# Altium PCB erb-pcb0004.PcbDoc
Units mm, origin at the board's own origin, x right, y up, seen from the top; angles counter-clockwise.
Board outline 37 x 24 mm, 4 copper layers (Top Layer, Signal_1, Signal_2, Top Bottom), stack 1.57 mm thick; 26 components, 49 nets, 129 pads, 38 vias.
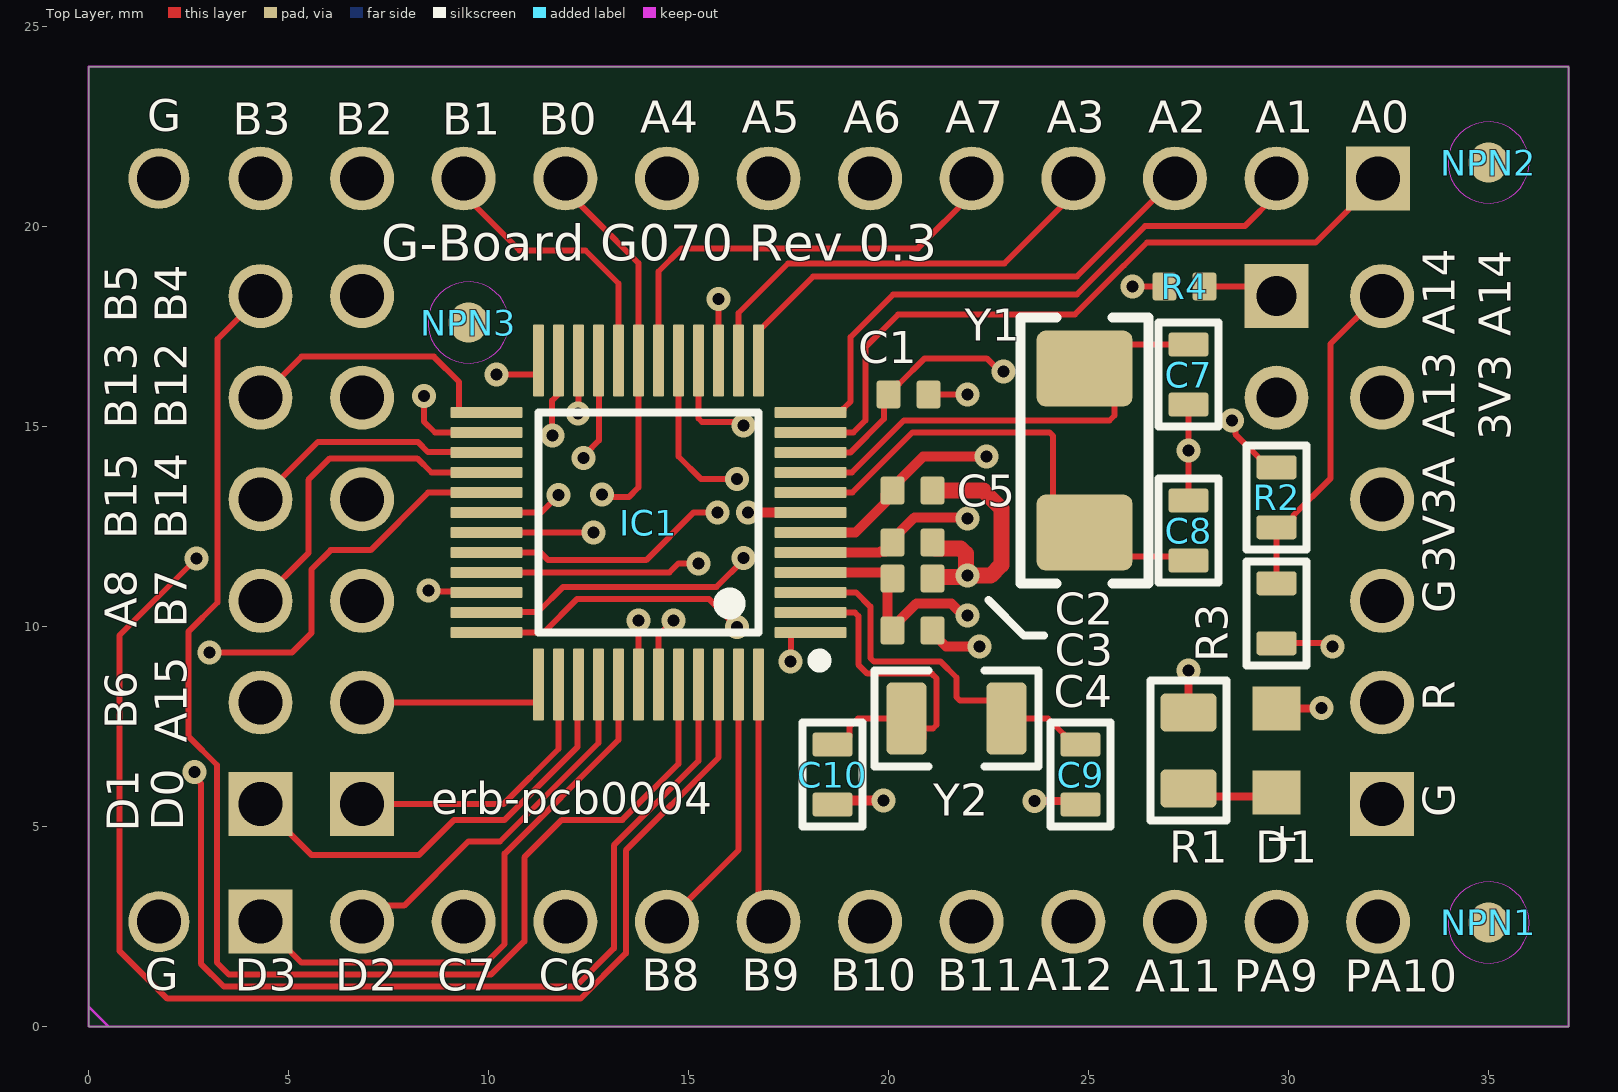
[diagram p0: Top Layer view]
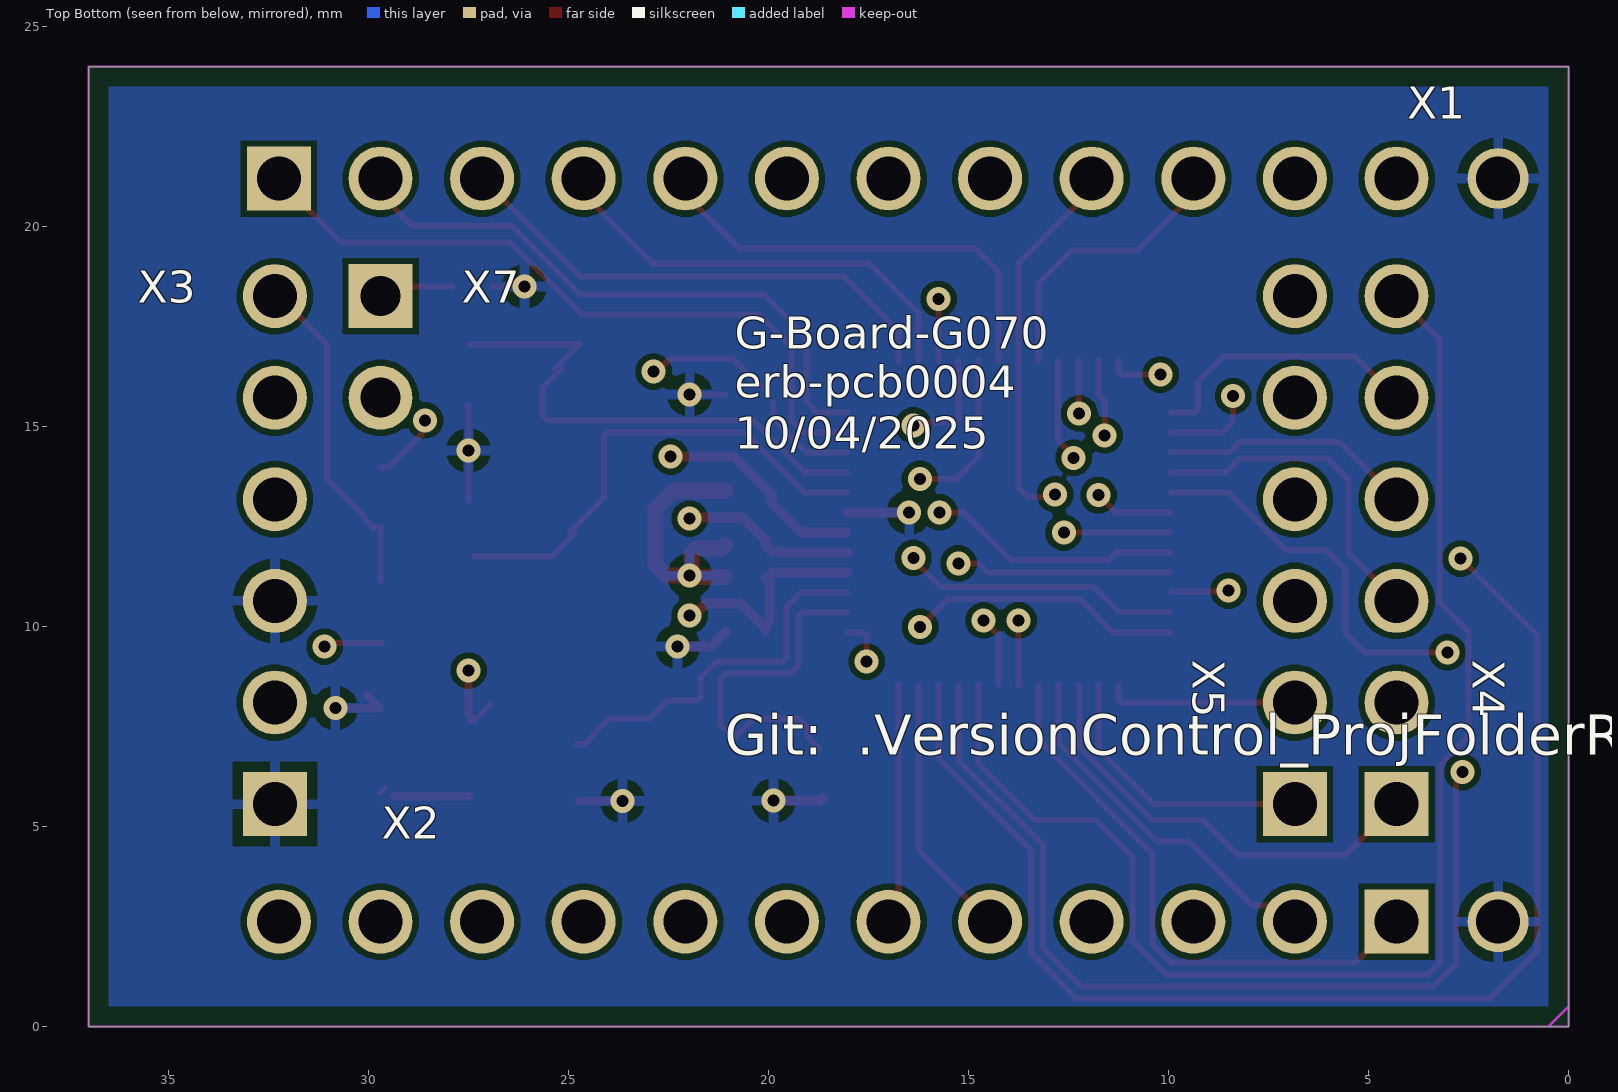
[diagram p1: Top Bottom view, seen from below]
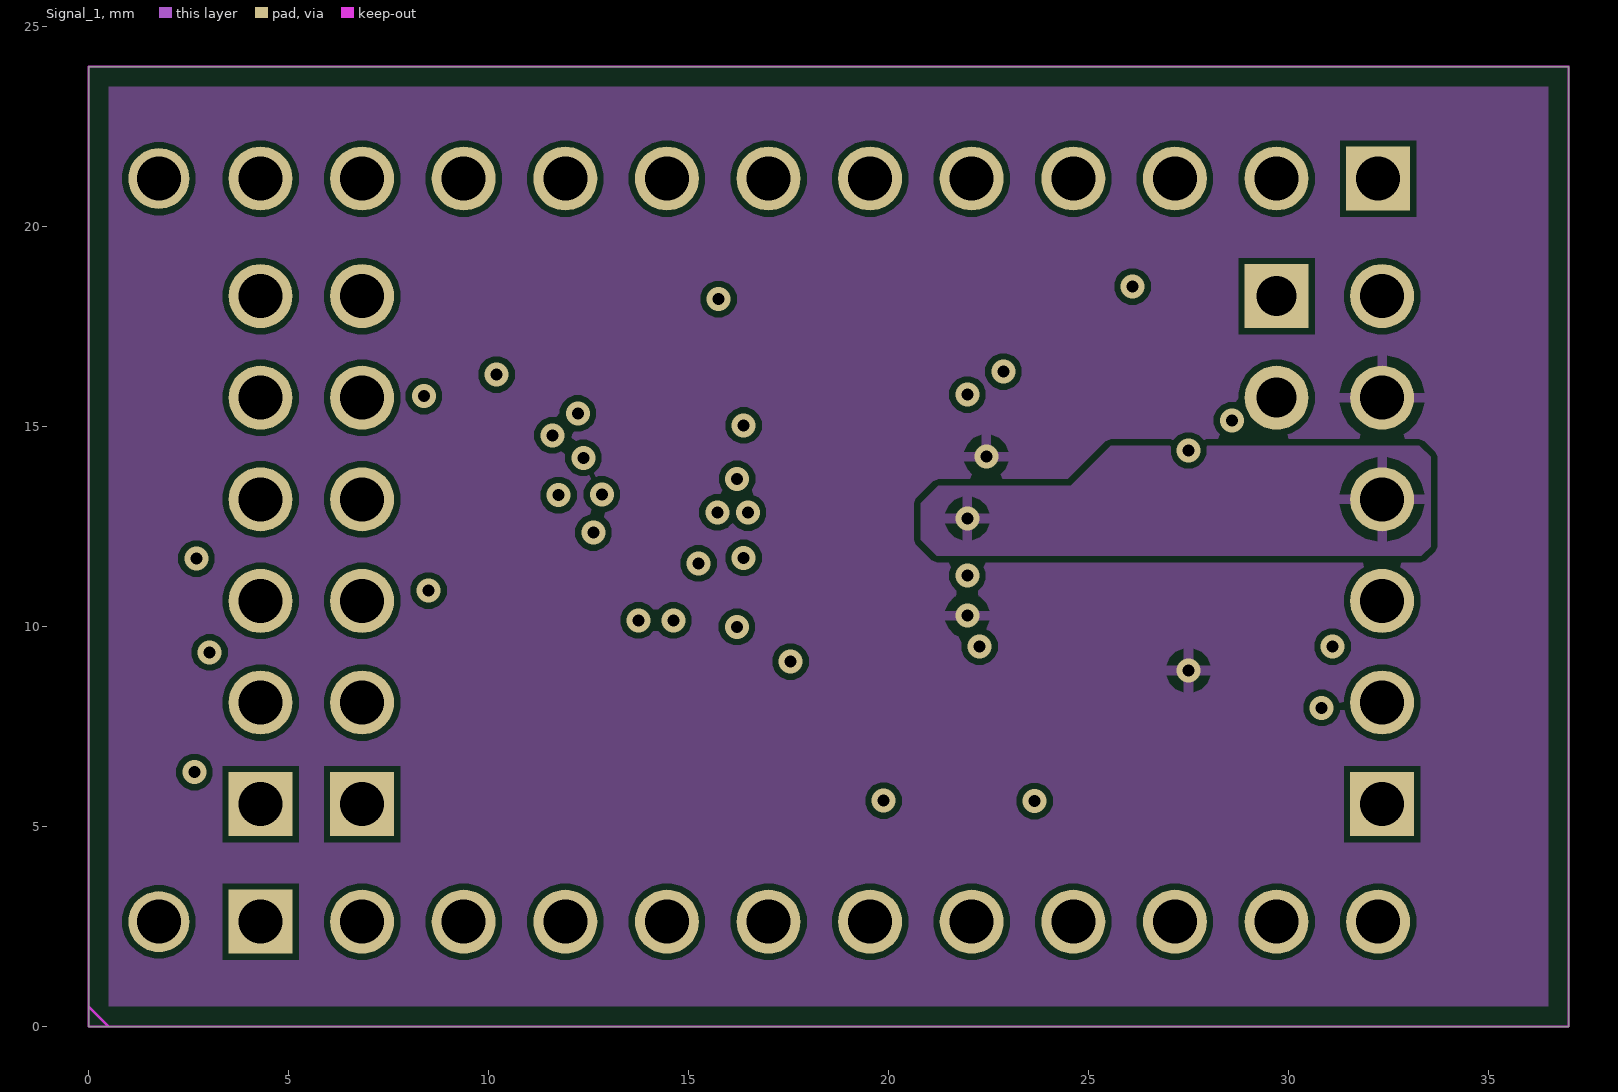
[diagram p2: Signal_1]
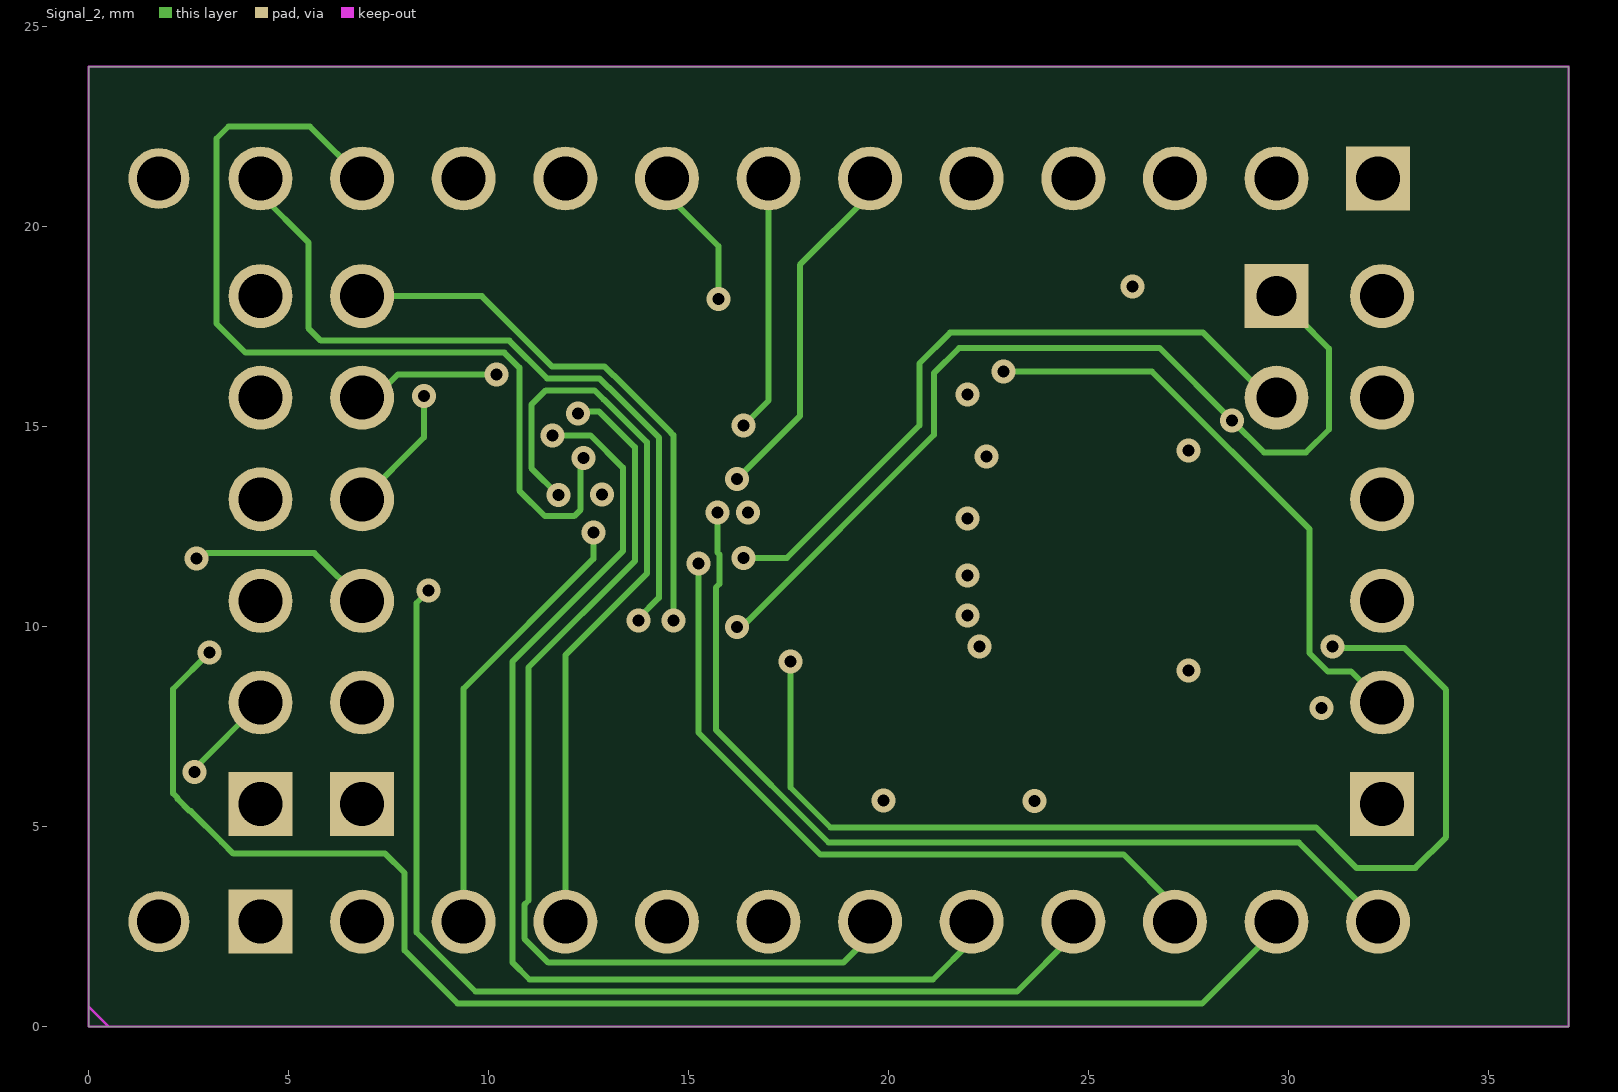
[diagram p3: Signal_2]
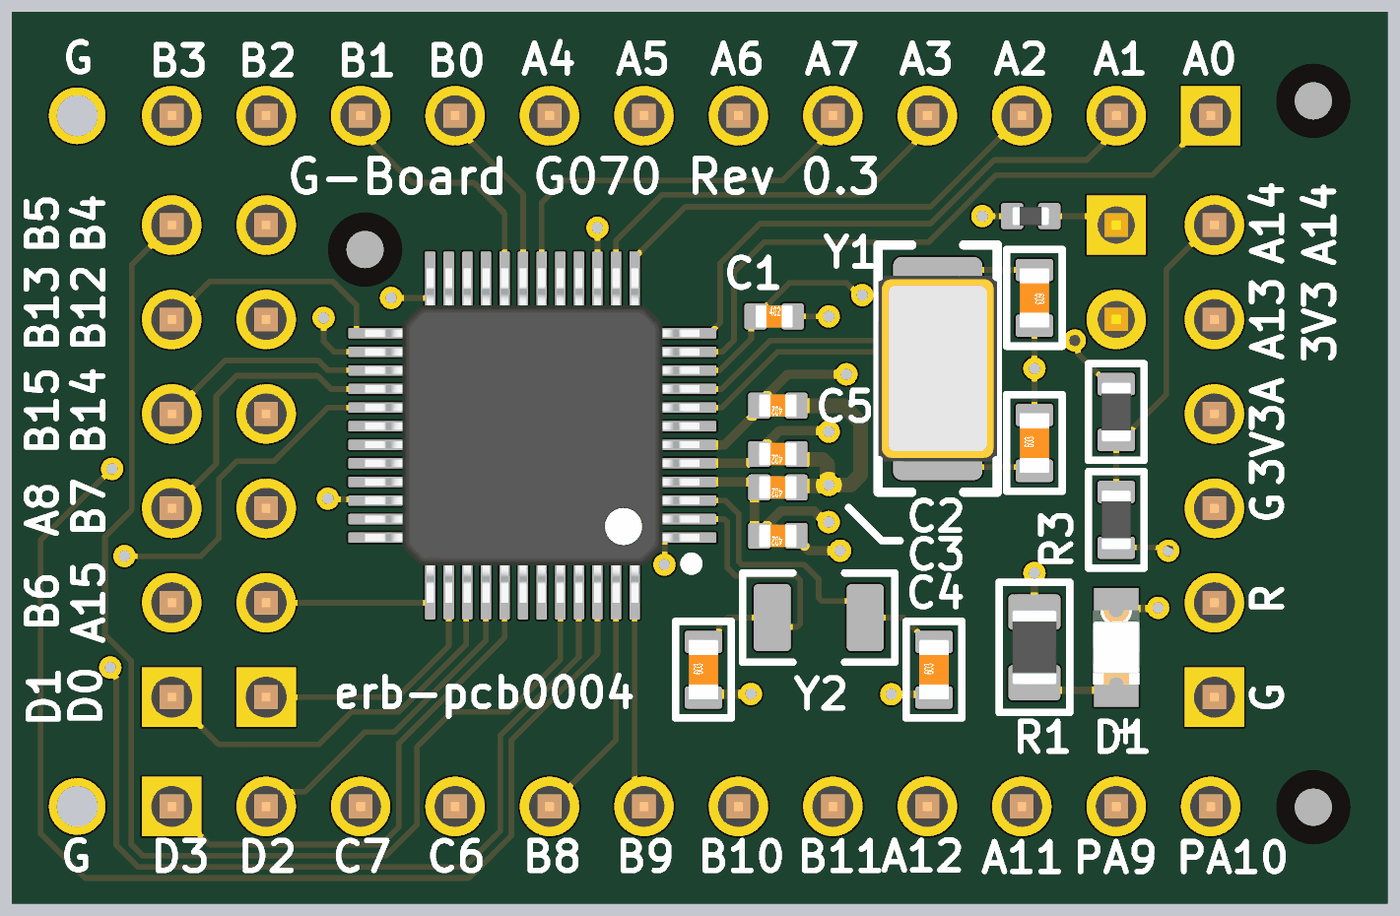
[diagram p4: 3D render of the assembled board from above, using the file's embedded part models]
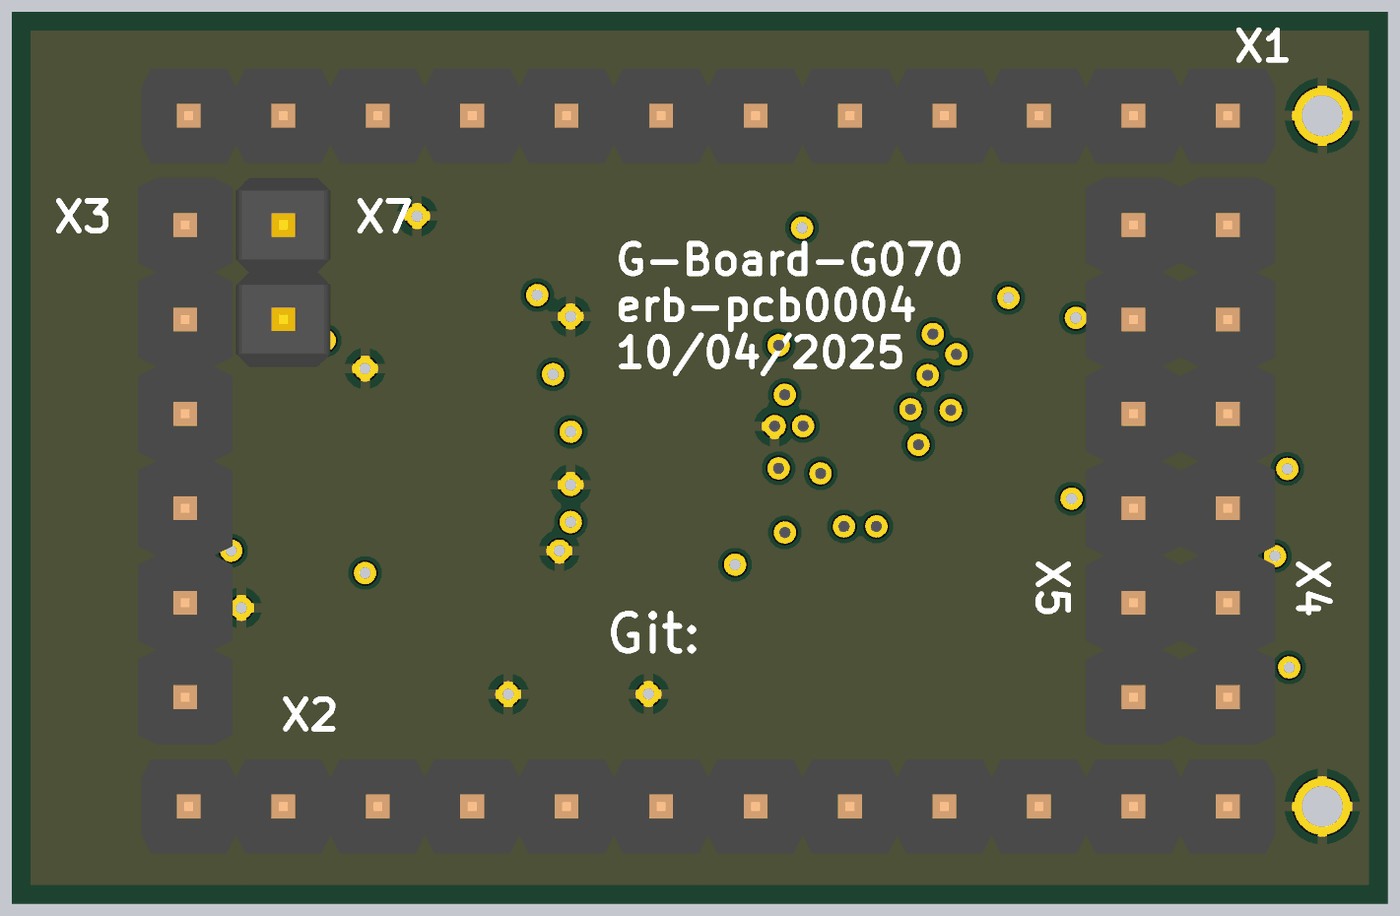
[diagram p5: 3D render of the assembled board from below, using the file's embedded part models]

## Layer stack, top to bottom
Top Solder: solder mask 0.0254, Solder Resist, Dk 3.5
Top Layer: signal copper 0.035
Dielectric 2: prepreg 0.2, PP-006, Dk 4.1
Signal_1: signal copper 0.0175
Dielectric 1: core 1.065, FR-4, Dk 4.6
Signal_2: signal copper 0.0175
Dielectric 3: prepreg 0.2, PP-006, Dk 4.1
Top Bottom: signal copper 0.035
Bottom Solder: solder mask 0.0254, Solder Resist, Dk 3.5

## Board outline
0,24 37,24 37,0 0,0

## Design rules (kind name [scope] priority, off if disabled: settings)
AssemblyTestPointUsage AssemblyTestPointUsage_1 [All] p2:
AssemblyTestpoint AssemblyTestpoint_1 [All] p2: testpointundercomponent=TRUE minsize=1.016 maxsize=2.54 preferedsize=1.524 minholesize=0 maxholesize=1.016 preferedholesize=0.813 testpointgrid=0.025 usegrid=TRUE gridtolerance=0 allowsidetop=TRUE allowsidebottom=TRUE
BoardOutlineClearance [All] p1: gap=0.5 ignorepadtopadclearanceinfootprint=FALSE except(0: Text-OutlineEdge Text-CavityEdge Text-CutoutEdge Text-SplitBarrior Text-SplitContinuation)
Clearance [All] p1: gap=0.15 ignorepadtopadclearanceinfootprint=TRUE
ComponentClearance [All] p1 off: gap=0.254 collisioncheckmode=3 verticalgap=0.254 showdistances=FALSE
DiffPairsRouting [All] p1: maxlimit=0.15 minlimit=0.15 mostfreqgap=0.15 toplayer_minwidth=0.25 toplayer_maxwidth=0.25 toplayer_prefwidth=0.25 midlayer1_minwidth=0.175 midlayer1_maxwidth=0.175 midlayer1_prefwidth=0.175 midlayer2_minwidth=0.175 midlayer2_maxwidth=0.175 midlayer2_prefwidth=0.175 bottomlayer_minwidth=0.25 bottomlayer_maxwidth=0.25 bottomlayer_prefwidth=0.25 impedanceprofiledriven=TRUE impedanceprofileid={FBCF767A-6538-404B-8383-ADABDCF97456} impedanceprofilevalue=90.000000 maxuncoupledlength=12.7
FabricationTestPointUsage FabricationTestPointUsage_1 [All] p2: valid=0 allowmultiple=FALSE
FabricationTestpoint FabricationTestpoint_1 [All] p2: side=3 testpointundercomponent=TRUE minsize=1.016 maxsize=2.54 preferedsize=1.524 minholesize=0 maxholesize=1.016 preferedholesize=0.813 testpointgrid=0.025 allowsidetop=TRUE allowsidebottom=TRUE usegrid=TRUE gridtolerance=0
FanoutControl Fanout_LCC [IsLCC] p1: bgadir=Out bgaviamode=Centered fanoutstyle=Auto fanoutdirection=Alternating viagrid=0.025 // Fanout_LCC (Default Rule)
FanoutControl Fanout_BGA [IsBGA] p2: bgadir=Out bgaviamode=Centered fanoutstyle=Auto fanoutdirection=Alternating viagrid=0.025 // Fanout_BGA (Default Rule)
FanoutControl Fanout_Default [All] p4: bgadir=Out bgaviamode=Centered fanoutstyle=Auto fanoutdirection=Alternating viagrid=0.025 // Fanout_Default (Default Rule)
FanoutControl Fanout_Small [(CompPinCount < 5)] p5: bgadir=Out bgaviamode=Centered fanoutstyle=Auto fanoutdirection=OutThenIn viagrid=0.025 // Fanout_Small (Default Rule)
FanoutControl Fanout_BGA_1 [IsBGA] p6: bgadir=Out bgaviamode=Centered fanoutstyle=Auto fanoutdirection=Alternating viagrid=0.025 // Fanout_BGA (Default Rule)
FanoutControl Fanout_LCC_1 [IsLCC] p7: bgadir=Out bgaviamode=Centered fanoutstyle=Auto fanoutdirection=Alternating viagrid=0.025 // Fanout_LCC (Default Rule)
FanoutControl Fanout_SOIC_1 [IsSOIC] p8: bgadir=Out bgaviamode=Centered fanoutstyle=Auto fanoutdirection=Alternating viagrid=0.025 // Fanout_SOIC (Default Rule)
FanoutControl Fanout_Small_1 [(CompPinCount < 5)] p9: bgadir=Out bgaviamode=Centered fanoutstyle=Auto fanoutdirection=OutThenIn viagrid=0.025 // Fanout_Small (Default Rule)
FanoutControl Fanout_Default_1 [All] p10: bgadir=Out bgaviamode=Centered fanoutstyle=Auto fanoutdirection=Alternating viagrid=0.025 // Fanout_Default (Default Rule)
Height [All] p1: minheight=0 maxheight=500 prefheight=12.7
HoleSize HoleSize_1 [All] p1: absolutevalues=TRUE maxlimit=6 minlimit=0.025 maxpercent=80.000 minpercent=20.000
HoleToHoleClearance [All] p1: gap=0.2 allowstackedmicrovias=TRUE
MinimumAnnularRing [All] p1: minimumring=0.15
MinimumSolderMaskSliver MinimumSolderMaskSliver_1 [All] p1: minsoldermaskwidth=0.1
PlaneClearance PlaneClearance_1 [All] p2: clearance=0.508
PlaneConnect PlaneConnect_1 [All] p2: planeconnectstyle=Relief reliefexpansion=50 reliefentries=4 reliefconductorwidth=2 reliefairgap=0.2
PlaneConnect Via [IsVia] p3: planeconnectstyle=Direct reliefexpansion=0.508 reliefentries=4 reliefconductorwidth=0.254 reliefairgap=0.254
PolygonConnect PolygonConnect_2 [OnLayer('Top Layer')] p1: thpad.connectstyle=Relief thpad.reliefconductorwidth=0.254 thpad.reliefentries=4 thpad.polygonreliefangle="90 Angle" thpad.airgapwidth=0.254 smdpad.connectstyle=NoConnect smdpad.reliefconductorwidth=0.254 smdpad.reliefentries=4 smdpad.polygonreliefangle="90 Angle" smdpad.airgapwidth=0.254 via.connectstyle=Relief via.reliefconductorwidth=0.254 via.reliefentries=4 via.polygonreliefangle="90 Angle" via.airgapwidth=0.254
PolygonConnect [All] p2: connectstyle=Relief reliefconductorwidth=0.254 reliefentries=4 polygonreliefangle="90 Angle" airgapwidth=0.254
PolygonConnect Polygon [IsVia] p3: connectstyle=Direct reliefconductorwidth=0.25 reliefentries=4 polygonreliefangle="90 Angle" airgapwidth=0.25
PolygonConnect PolygonConnect_1 [All] p4: connectstyle=Relief reliefconductorwidth=0.254 reliefentries=4 polygonreliefangle="90 Angle" airgapwidth=0.254
RoomDefinition Main [InComponentClass('Main')] p1: confinementstyle=ConfineIn formatcopy=TRUE lockcomponents=FALSE outline -102.73,-40.2 -51.93,-40.2 -51.93,-14.8 -102.73,-14.8
RoutingVias RoutingVias_1 [All] p1: holewidth=0.3 width=0.6 viastyle="Through Hole" minholewidth=0.3 minwidth=0.6 maxholewidth=0.3 maxwidth=0.6
SilkToSilkClearance SilkToSilkClearance_1 [All] p1 off: silktosilkclearance=0
SolderMaskExpansion SolderMaskExpansion_VIA [IsVia] p1: expansion=0 istentingtop=FALSE soldermaskfromhole=TRUE
SolderMaskExpansion SolderMaskExpansion_1 [All] p2: expansion=0.05 istentingtop=FALSE
Width Width_1 [InNetClass('SD_CARD')] p1: maxlimit=0.35 minlimit=0.27 preferedwidth=0.35 toplayer_minwidth=0.35 midlayer1_maxwidth=0.27 midlayer1_prefwidth=0.27 midlayer2_maxwidth=0.27 midlayer2_prefwidth=0.27 bottomlayer_minwidth=0.35 impedanceprofiledriven=TRUE impedanceprofileid={85F77CA9-F07E-4DD7-AF50-05B7DE60F978} impedanceprofilevalue=50.000000 minimp=50.000000 maximp=50.000000 favimp=50.000000
Width [All] p2: maxlimit=1 minlimit=0.15 preferedwidth=0.3 minimp=50.000000 maximp=50.000000 favimp=50.000000
19 further rules are at their usual default settings.

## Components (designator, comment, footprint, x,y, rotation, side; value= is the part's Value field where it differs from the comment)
C1 "100nF" CAPC1005X55 20.5,15.8 r0 top
C2 "100nF" CAPC1005X55 20.6,12.1 r180 top
C3 "100nF" CAPC1005X55 20.6,11.2 r180 top
C4 "1uF" CAPC1005X55 20.6,9.9 r180 top
C5 "100nF" CAPC1005X55 20.6,13.4 r180 top
C7 "22pF" CAPC1608X95N 27.5,16.3 r270 top
C8 "22pF" CAPC1608X95N 27.5,12.4 r90 top
C9 "8.2pF" CAPC1608X95N 24.8,6.3 r90 top
C10 "8.2pF" CAPC1608X95N 18.6,6.3 r90 top
D1 "RED" WL-SMCW_0805 29.7,6.9 r270 top
IC1 "STM32G070CBT6" LQFP-48_7x7x05P 14,12.6 r90 top locked
NPN1 "FID" Fiducial_1mm 35,2.6 r90 top
NPN2 "FID" Fiducial_1mm 35,21.6 r90 top
NPN3 "FID" Fiducial_1mm 9.5,17.6 r90 top
R1 "130R" RESC2012X70N 27.5,6.9 r270 top
R2 "0R" RESC1608X55N 29.7,13.23 r270 top
R3 "DNP" RESC1608X55N 29.7,10.33 r270 top
R4 "100k" RESC1005X40N 27.4,18.5 r180 top
X1 "HDR 1x12" 61301211121_no 18.27,21.2 r180 bottom
X2 "HDR 1x12" 61301211121_no 18.27,2.62 r0 bottom
X3 "HDR 1x6" 61300611121_no 32.34,11.91 r90 bottom
X4 "HDR 1x6" 61300611121_no 4.3,11.91 r90 bottom
X5 "HDR 1x6" 61300611121_no 6.84,11.91 r90 bottom
X7 "HDR 1x2" CON_HEADER2.54_1X2W_NO 29.7,15.72 r180 bottom
Y1 "8MHz ±20ppm 20pF" SMD-5032_2P 24.9,14.4 r90 top
Y2 "32.768KHz ±20ppm 12.5pF" "SMD-3215_2P FC - 135" 21.7,7.7 r180 top

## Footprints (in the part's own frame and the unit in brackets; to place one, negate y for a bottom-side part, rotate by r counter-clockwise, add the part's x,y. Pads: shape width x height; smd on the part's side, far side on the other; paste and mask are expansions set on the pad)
61300611121_no [mm] "Pin Header, pitch 2.54 mm, THT, Vertical, single row, 6p"
  rect 1.6x1.6 hole 1.1: 1(-6.35,0)
  round 1.6 hole 1.1: 2(-3.81,0) 3(-1.27,0) 4(1.27,0) 5(3.81,0) 6(6.35,0)
  body extent -7.62,-1.27 7.62,1.27, height 8.57
61301211121_no [mm] "Pin Header, pitch 2.54 mm, THT, Vertical, single row, 12p"
  rect 1.6x1.6 hole 1.1: 1(-13.97,0)
  round 1.6 hole 1.1: 2(-11.43,0) 3(-8.89,0) 4(-6.35,0) 5(-3.81,0) 6(-1.27,0) 7(1.27,0) 8(3.81,0) 9(6.35,0) 10(8.89,0) 11(11.43,0) 12(13.97,0)
  body extent -15.24,-1.27 15.24,1.27, height 8.57
CAPC1005X55 [mm] "Chip Capacitor, 2-Leads, Body 1,0x0,5mm, imperial 0402"
  rrect25% 0.6x0.7 smd: 1(-0.5,0) 2(0.5,0)
  body extent -0.5,-0.3 0.5,0.3, height 0.55
CAPC1608X95N [mm] "Chip Capacitor, 2-Leads, Body 1,6x0,8mm, imperial 0603"
  rrect25% 0.6x1 smd: 1(-0.75,0) 2(0.75,0)
  silkscreen extent -1.3,-0.75 1.3,0.75, body extent -0.8,-0.4 0.8,0.4, height 0.3
CON_HEADER2.54_1X2W_NO [mm]
  rect 1.6x1.6 hole 1: 1(0,2.54)
  round 1.6 hole 1: 2(0,0)
  body extent -1.27,-1.27 1.27,3.81, height 9.51
Fiducial_1mm [mm]
  round 1 smd mask+0.5: 0(0,0)
  Top Layer keep-out circle w0.01: c0,0 r1.016
LQFP-48_7x7x05P [mm]
  rrect25% 0.28x1.8 smd mask+0.051: 1(-2.75,-4.05) 2(-2.25,-4.05) 3(-1.75,-4.05) 4(-1.25,-4.05) 5(-0.75,-4.05) 6(-0.25,-4.05) 7(0.25,-4.05) 8(0.75,-4.05) 9(1.25,-4.05) 10(1.75,-4.05) 11(2.25,-4.05) 12(2.75,-4.05) 25(2.75,4.05) 26(2.25,4.05) 27(1.75,4.05) 28(1.25,4.05) 29(0.75,4.05) 30(0.25,4.05) 31(-0.25,4.05) 32(-0.75,4.05) 33(-1.25,4.05) 34(-1.75,4.05) 35(-2.25,4.05) 36(-2.75,4.05)
  rrect25% 1.8x0.28 smd mask+0.051: 13(4.05,-2.75) 14(4.05,-2.25) 15(4.05,-1.75) 16(4.05,-1.25) 17(4.05,-0.75) 18(4.05,-0.25) 19(4.05,0.25) 20(4.05,0.75) 21(4.05,1.25) 22(4.05,1.75) 23(4.05,2.25) 24(4.05,2.75) 37(-4.05,2.75) 38(-4.05,2.25) 39(-4.05,1.75) 40(-4.05,1.25) 41(-4.05,0.75) 42(-4.05,0.25) 43(-4.05,-0.25) 44(-4.05,-0.75) 45(-4.05,-1.25) 46(-4.05,-1.75) 47(-4.05,-2.25) 48(-4.05,-2.75)
  silkscreen extent -3.6,-4.42 2.75,2.75, body extent -4.5,-4.5 4.5,4.5, height 1.6
RESC1005X40N [mm] "Chip Resistor, 2-Leads, Body 1,0x0,5mm, imperial 0402"
  rrect25% 0.6x0.7 smd: 1(-0.5,0) 2(0.5,0)
  body extent -0.5,-0.25 0.5,0.25, height 0.4
RESC1608X55N [mm] "Chip Resistor, 2-Leads, Body 1,6x0,85mm, imperial 0603"
  rrect25% 0.6x1 smd: 1(-0.75,0) 2(0.75,0)
  silkscreen extent -1.3,-0.75 1.3,0.75, body extent -0.8,-0.4 0.8,0.4, height 0.55
RESC2012X70N [mm] "Chip Resistor, 2-Leads, Body 2,0x1,25mm, imperial 0805"
  rrect25% 0.95x1.4 smd: 1(-0.95,0) 2(0.95,0)
  silkscreen extent -1.75,-0.95 1.75,0.95, body extent -1,-0.6 1,0.6, height 0.7
"SMD-3215_2P FC - 135" [mm]
  rrect25% 1x1.8 smd: 1(-1.25,0) 2(1.25,0)
  silkscreen extent -2.05,-1.2 2.05,1.2
SMD-5032_2P [mm]
  rrect25% 1.9x2.4 smd: 1(-2.05,0) 2(2.05,0)
  silkscreen extent -3.32,-1.6 3.32,1.6, body extent -2.5,-1.6 2.5,1.6, height 0.95
WL-SMCW_0805 [mm] "SMD Mono-color Chip LED, body 2.0x1.25mm"
  rect 1.1x1.2 smd: A(1.05,0) K(-1.05,0)
  body extent -1,-0.63 1,0.62, height 0.7

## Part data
C1 C2 C3 C5: library part CAP_100nF_0402, "X7R 100nF ±10% 16V 0402 Multilayer Ceramic Capacitors MLCC - SMD/SMT ROHS", JLC=C1525, Manufacturer="Samsung Electro-Mechanics", Manufacturer Part Number=CL05B104KO5NNNC, Tolerance=10%, Voltage Rating=16VDC
C4: library part CAP_1uF_0402, "X5R 25V ±10% 1uF 0402 Multilayer Ceramic Capacitors MLCC - SMD/SMT ROHS", JLC=C52923, Manufacturer="Samsung Electro-Mechanics", Manufacturer Part Number=CL05A105KA5NQNC, Tolerance=10%, Voltage Rating=25V
C7 C8: library part CAP_22pF_50V_0603, "Chip capacitors", JLC=C1653, Manufacturer="Samsung Electro-Mechanics", Manufacturer Part Number=CL10C220JB8NNNC, Voltage Rating=50V
C9 C10: library part CAP_8p2_50V_0603, "Multilayer Ceramic Capacitors MLCC - SMD/SMT 0402 8.0pF 50volts C0G +/-0.5pF", JLC=C1685, Manufacturer="Guangdong Fenghua Advanced Tech", Manufacturer Part Number=0603CG8R2C500NT, Voltage Rating=50V
D1: library part LED_0805_RED_AK, "Standard LEDs - SMD WL-SMCW SMDMono TpVw Waterclr 0805 Red", JLC=C84256, Manufacturer="Wurth Elektronik", Manufacturer Part Number=150080RS75000, Voltage Rating=2.0
IC1: "ARM Mikrocontroller - MCU Mainstream Value line, Arm Cortex-M0+ MCU 128 Kbytes of Flash 36 Kbytes RAM, 64", JLC=C529338, Manufacturer=STMicroelectronics
NPN1 NPN2 NPN3: library part Fiducial_1mm
R1: library part RES_130R_0805, "Dickfilmwiderstände - SMD 1/8watt 130ohms 1% 100ppm", JLC=C17437, Manufacturer="Vishay / Dale", Manufacturer Part Number=CRCW0805130RFKEA, Tolerance=1%, Voltage Rating=150V
R2: library part RES_0R_0603, "Thick Film Resistors - SMD 1/10watt ZEROohm Jumper", JLC=C21189, Manufacturer=Vishay, Manufacturer Part Number=CRCW06030000Z0EA, Tolerance=1%, Voltage Rating=75V
R3: library part RES_DNF_0603, "Resistor SMD 0603 - not populated"
R4: library part RES_100k_0402, "Thick Film Resistors - SMD 63mW 100Kohms 1%", JLC=C60491, Manufacturer=Vishay, Manufacturer Part Number=RC0402FR-07100KL, Tolerance=1%, Voltage Rating=50V
X1 X2: library part CON_HEADER_1X12_no_overlay, "Board-to-Board-Steckverbinder, 2.54 mm, 12 Kontakt(e), Stiftleiste 1-Reihig", Manufacturer=WE, Manufacturer Part Number=61301211121
X3 X4 X5: library part CON_HEADER_1X6_no_overlay, "Board-to-Board-Steckverbinder, 2.54 mm, 6 Kontakt(e), Stiftleiste 1-Reihig", Manufacturer=WE, Manufacturer Part Number=61300611121
X7: library part CON_HEADER_1X2_no_overlay, "Board-to-Board-Steckverbinder, 2.54 mm, 2 Kontakt(e), Stiftleiste 1-Reihig", Lumira Part Number=S-QMS-SPEC-32507, Manufacturer=Samtec, Manufacturer Part Number=TSW-102-07-T-S
Y1: library part "SMD-5032_2P 8MHz 20ppm 20pF", "8MHz SMD Crystal Resonator 20pF ±10ppm ±50ppm -40℃~+85℃ SMD5032-2P Crystals ROHS", JLC=C115962, Manufacturer="Yangxing Tech", Manufacturer Part Number=X50328MSB2GI, Package=SMD-5032_2P
Y2: library part "SMD-3215_2P 32.768KHz 20ppm 12.5pF", "32.768kHz SMD Crystal Resonator 12.5pF 70kΩ ±20ppm -40℃~+85℃ SMD3215-2P Crystals ROHS", JLC=C32346, Manufacturer="Seiko Epson", Manufacturer Part Number=Q13FC1350000400, Package=SMD-3215_2P

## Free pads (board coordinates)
  round 1.524 hole 1.1: 2(1.76,2.62) 2(1.76,21.2)

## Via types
v1: diameter 0.6, hole 0.3, Top Layer to Top Bottom, 38 vias

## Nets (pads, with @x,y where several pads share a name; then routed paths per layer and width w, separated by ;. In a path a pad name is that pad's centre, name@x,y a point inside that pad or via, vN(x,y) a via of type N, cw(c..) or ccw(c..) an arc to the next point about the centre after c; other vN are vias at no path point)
3V3: C3.2 C4.2 C5.2 IC1.4 IC1.6 R1.1 X3.5 | length 12.9
  Top Layer w0.15: R1.1@26.964,8.047 27.36,7.65 R1.1@27.47,7.65
  Top Layer w0.2: R1.1@27.425,7.715 27.5,7.79 v1(27.5,8.9)
  Top Layer w0.25: IC1.4@18.02,11.35 19.895,11.35 C3.2@20.058,11.188 ; IC1.6 19.175,12.35 19.925,13.1 19.925,13.305 20.865,14.245 v1(22.445,14.245) ; C4.2@20.07,9.9 C4.2@20.07,9.95 ; C3.2@20.07,11.2 C3.2@20.058,11.188 ; v1(21.97,10.27) 21.875,10.27 21.57,10.575 20.695,10.575 20.12,10 20.095,10 19.97,10.125 19.97,11.1 C3.2@20.058,11.188
3V3A: C2.2 IC1.5 X3.4 | length 4.4
  Top Layer w0.25: IC1.5@18.02,11.85 19.779,11.85 19.804,11.875 19.925,11.875 20.07,12.02 20.07,12.15 20.645,12.725 21.945,12.725 v1(21.97,12.7)
GND: C1.2 C2.1 C3.1 C4.1 C5.1 C7.2 C8.2 C9.1 C10.1 D1.K IC1.7 pad.2 R4.2 X3.1 X3.3 | length 17.9
  Top Layer w0.15: C1.2@21.07,15.8 v1(21.97,15.8) ; v1(26.1,18.5) R4.2 ; C8.2 v1(27.5,14.4) 27.5,15.541 C7.2@27.525,15.541
  Top Layer w0.2: v1(23.65,5.638) C9.1@24.75,5.638 ; D1.K@30.05,8.3 D1.K 30.815,7.95 v1(30.828,7.963)
  Top Layer w0.25: v1@16.36,12.725 v1(16.485,12.85) IC1.7@18.02,12.85 ; C10.1@18.64,5.713 18.707,5.645 v1(19.877,5.645) ; C4.1@21.07,9.87 21.08,9.87 21.275,9.675 21.275,9.665 21.44,9.5 v1(22.275,9.5) ; C3.1@21.07,11.2 C3.1@21.105,11.235 ; v1@21.935,11.235 v1(21.97,11.27)
  Top Layer w0.4: C2.1@21.07,12.05 21.17,11.95 21.805,11.95 21.932,11.823 21.932,11.308 v1(21.97,11.27) 22.551,11.27 22.82,11.539 22.82,12.95 22.37,13.4 C5.1 C5.1@21.07,13.4 ; C3.1@21.105,11.235 v1@21.935,11.235
NetC7_1: C7.1 IC1.9 Y1.2 | length 13.2
  Top Layer w0.15: IC1.9@18.02,13.85 IC1.9 19.085,13.85 20.385,15.15 25.525,15.15 25.65,15.275 25.65,15.97 Y1.2@25.17,16.45 ; Y1.2@25.332,16.45 24.726,17.056 C7.1@27.475,17.056
NetC8_1: C8.1 IC1.8 Y1.1 | length 12.3
  Top Layer w0.15: IC1.8@18.02,13.35 19.096,13.35 20.596,14.85 24.028,14.85 24.116,14.762 24.116,13.213 Y1.1@24.979,12.35 ; Y1.1@24.82,12.35 25.425,11.745 C8.1@27.365,11.745
NetC9_2: C9.2 IC1.3 Y2.1 | length 9.4
  Top Layer w0.15: IC1.3@18.02,10.85 IC1.3 19.19,10.85 19.545,10.495 19.545,9.501 19.55,9.496 19.55,9.209 19.638,9.122 21.303,9.122 21.7,8.724 21.7,8.233 21.788,8.145 22.529,8.145 22.95,7.724 Y2.1 23.988,7.7 24.375,7.313 24.375,7.275 24.6,7.05 C9.2
NetC10_2: C10.2 IC1.2 Y2.2 | length 8.9
  Top Layer w0.15: IC1.2@18.02,10.35 IC1.2 19.157,10.35 19.245,10.262 19.245,9.048 19.471,8.822 21.082,8.822 21.2,8.704 21.2,7.538 21.112,7.45 20.871,7.45 20.871,7.205 20.45,7.626 Y2.2 ; C10.2@18.74,6.961 19.025,7.246 19.025,7.487 19.238,7.7 Y2.2@20.22,7.7
NetD1_A: D1.A R1.2 | length 2
  Top Layer w0.15: D1.A@29.6,5.95 D1.A
  Top Layer w0.2: R1.2@27.47,5.75 D1.A@29.37,5.75
NetR2_2: R2.2 R3.1 X3.6 | length 8.3
  Top Layer w0.15: R3.1@29.7,11.145 R2.2 29.9,12.48 30.125,12.705 30.125,12.78 31.044,13.699 31.044,17.064 X3.6@32.24,18.26
PA0: IC1.11 X1.1 | length 17.9
  Top Layer w0.15: IC1.11@18.02,14.85 19.12,14.85 19.42,15.15 19.42,16.981 20.239,17.8 24.658,17.8 25.883,19.025 25.888,19.025 26.463,19.6 30.677,19.6 32.24,21.163 X1.1
PA1: IC1.12 X1.2 | length 14.9
  Top Layer w0.15: IC1.12@18.02,15.35 18.81,15.35 18.875,15.415 18.875,15.45 19.051,15.626 19.051,17.237 20.114,18.3 24.706,18.3 26.413,20.007 28.907,20.007 X1.2@29.7,20.8
PA2: IC1.13 X1.3 | length 12.7
  Top Layer w0.15: IC1.13 16.75,17.383 18.117,18.75 24.71,18.75 X1.3
PA3: IC1.14 X1.4 | length 10.8
  Top Layer w0.15: IC1.14 16.25,17.839 17.486,19.075 22.895,19.075 X1.4@24.62,20.8
PA4: IC1.15 X1.8 | length 4.8
  Top Layer w0.15: X1.8@14.46,20.69 X1.8@14.46,20.8 ; IC1.15 v1(15.75,18.186)
  Signal_2 w0.15: X1.8@14.46,20.8 15.75,19.51 v1(15.75,18.186)
PA5: IC1.16 X1.7 | length 8.8
  Top Layer w0.15: IC1.16 15.25,15.2 15.338,15.112 16.294,15.112 v1(16.38,15.026) ; X1.7@17,20.73 X1.7@17,20.8
  Signal_2 w0.15: v1(16.38,15.026) 17,15.646 X1.7@17,20.8
PA6: IC1.17 X1.6 | length 12.6
  Top Layer w0.15: IC1.17 14.75,14.25 15.307,13.693 v1(16.214,13.693)
  Signal_2 w0.15: v1(16.214,13.693) 17.781,15.261 17.781,19.041 X1.6@19.54,20.8
PA7: IC1.18 X1.5 | length 10.9
  Top Layer w0.15: IC1.18 14.25,17.291 14.25,18.875 14.83,19.455 20.735,19.455 X1.5@22.08,20.8
PA8: IC1.28 X4.3 | length 8.3
  Top Layer w0.15: X4.3 5.496,11.836 5.496,13.668 6.033,14.205 8.218,14.205 8.573,13.85 IC1.28
PA9: IC1.29 X2.11 | length 45.5
  Top Layer w0.15: v1(3.03,9.355) 5.091,9.355 5.57,9.834 5.57,11.424 6.056,11.91 7.052,11.91 8.492,13.35 IC1.29
  Signal_2 w0.15: v1(3.03,9.355) 2.112,8.437 2.112,5.83 2.225,5.717 2.225,5.692 2.533,5.385 2.558,5.385 3.325,4.617 3.619,4.323 7.417,4.323 7.9,3.84 7.9,1.905 9.23,0.575 20.623,0.575 27.841,0.575 X2.11@29.793,2.527 ; X2.11 X2.11@29.917,2.837
PA10: IC1.32 X2.12 | length 30.4
  Top Layer w0.15: IC1.32 11.303,11.85 11.492,11.661 13.939,11.661 15.13,12.852 v1(15.721,12.852)
  Signal_2 w0.15: v1(15.721,12.852) 15.721,11.851 15.775,11.797 15.775,11.065 15.685,10.975 15.685,7.415 18.5,4.6 30.26,4.6 X2.12
PA11: IC1.33 X2.10 | length 23.3
  Top Layer w0.15: IC1.33 14.52,11.35 14.75,11.58 v1(15.25,11.58)
  Signal_2 w0.15: v1(15.25,11.58) 15.25,7.347 18.297,4.3 25.88,4.3 X2.10@27.16,3.02
PA12: IC1.34 X2.9 | length 28.1
  Top Layer w0.15: v1(8.5,10.9) 8.519,10.881 9.919,10.881 IC1.34
  Signal_2 w0.15: v1(8.5,10.9) 8.5,10.887 8.2,10.587 8.2,2.35 9.675,0.875 20.499,0.875 23.217,0.875 24.62,2.278 X2.9
PA13: IC1.35 X7.2 | length 24.3
  Top Layer w0.15: IC1.35 9.963,10.363 11.238,10.363 11.865,10.99 15.7,10.99 16.38,11.67 v1(16.38,11.716)
  Signal_2 w0.15: v1(16.38,11.716) 17.461,11.716 20.77,15.024 20.77,16.575 21.54,17.345 27.868,17.345 29.493,15.72 X7.2
PA14: IC1.36 R2.1 R4.1 X7.1 | length 33.5
  Top Layer w0.15: IC1.36 11.377,9.85 12.217,10.69 15.51,10.69 v1(16.21,9.99) ; R4.1 29.46,18.5 X7.1 ; v1(28.585,15.154) 28.672,15.068 28.672,14.809 29.5,13.98 R2.1
  Signal_2 w0.15: v1(16.21,9.99) 16.332,9.99 16.49,10.149 16.494,10.149 21.133,14.788 21.133,16.332 21.765,16.964 26.776,16.964 v1(28.585,15.154) 29.387,14.353 30.438,14.353 31.012,14.927 31.012,16.948 X7.1@30.266,17.694
PA15: IC1.37 X5.2 | length 4.8
  Top Layer w0.15: X5.2 11.185,8.1 11.25,8.165 IC1.37
PB0: IC1.19 X1.9 | length 9.2
  Top Layer w0.15: X1.9@11.92,20.8 12.035,20.8 12.64,20.195 13.75,19.085 IC1.19 13.75,13.48 13.507,13.236 12.902,13.236 v1(12.833,13.305)
PB1: IC1.20 X1.10 | length 6.7
  Top Layer w0.15: X1.10@9.38,20.8 10.78,19.4 12.425,19.4 13.25,18.575 IC1.20
PB2: IC1.21 X1.11 | length 26.4
  Top Layer w0.15: X1.11@6.84,20.8 X1.11@7.17,20.8 ; v1@12.427,14.319 12.76,14.651 IC1.21@12.76,16.64
  Signal_2 w0.15: X1.11@6.84,20.8 6.84,21.192 5.532,22.5 3.5,22.5 3.2,22.2 3.2,17.573 3.924,16.848 10.394,16.848 10.773,16.47 10.773,13.396 11.411,12.757 12.139,12.757 12.301,12.919 12.301,14.149 v1(12.371,14.218)
PB3: IC1.42 X1.12 | length 20.1
  Top Layer w0.15: IC1.42@13.75,8.52 v1(13.75,10.154)
  Signal_2 w0.15: X1.12@4.3,20.8 5.496,19.604 5.496,17.46 5.808,17.148 10.518,17.148 11.461,16.206 12.773,16.206 12.998,15.981 13.008,15.981 14.258,14.731 14.258,10.715 13.75,10.207 v1(13.75,10.154)
PB4: IC1.43 X5.6 | length 15.6
  Top Layer w0.15: IC1.43 14.25,9.784 v1(14.62,10.154)
  Signal_2 w0.15: X5.6 9.831,18.26 11.585,16.506 12.897,16.506 13.122,16.281 13.132,16.281 14.558,14.855 14.558,14.845 14.62,14.783 v1(14.62,10.154)
PB5: IC1.44 X4.6 | length 34.6
  Top Layer w0.15: X4.6@4.19,18.15 3.223,17.184 3.223,10.599 2.505,9.881 2.505,7.246 3.212,6.539 3.212,1.595 3.512,1.295 10.06,1.295 10.895,2.13 10.895,4.228 11.832,5.165 13.347,5.165 14.75,6.568 IC1.44
PB6: IC1.45 X4.2 | length 25.7
  Top Layer w0.15: v1(2.649,6.36) 2.649,6.238 2.81,6.077 2.81,1.573 3.388,0.995 12.176,0.995 13.135,1.954 13.135,4.529 15.25,6.644 IC1.45
  Signal_2 w0.15: v1(2.649,6.36) 2.649,6.449 X4.2
PB7: IC1.46 X5.3 | length 36.6
  Top Layer w0.15: v1(2.698,11.7) 0.773,9.775 0.773,1.894 1.972,0.695 12.3,0.695 13.435,1.83 13.435,4.404 15.75,6.719 IC1.46
  Signal_2 w0.15: v1(2.698,11.7) 2.82,11.7 2.956,11.836 5.644,11.836 X5.3
PB8: IC1.47 X2.5 | length 6.7
  Top Layer w0.15: X2.5 16.25,4.41 IC1.47
PB9: IC1.48 X2.6 | length 5.6
  Top Layer w0.15: IC1.48 16.75,3.27 X2.6@17,3.02
PB10: IC1.22 X2.7 | length 26.1
  Top Layer w0.15: v1(12.232,15.329) 12.25,15.347 IC1.22
  Signal_2 w0.15: v1(12.232,15.329) 12.284,15.381 12.76,15.381 13.658,14.483 13.658,11.636 11,8.978 11,3.15 10.895,3.045 10.895,2.195 11.495,1.595 18.869,1.595 19.54,2.266 X2.7
PB11: IC1.23 X2.8 | length 30.1
  Top Layer w0.15: v1@11.592,14.786 11.592,15.65 11.75,15.807 IC1.23
  Signal_2 w0.15: v1(11.598,14.781) 12.551,14.781 13.358,13.974 13.358,11.886 10.595,9.123 10.595,1.605 11.025,1.175 21.112,1.175 22.08,2.143 X2.8
PB12: IC1.24 X5.5 | length 5
  Top Layer w0.15: v1(10.2,16.3) 11.185,16.3 11.25,16.365 IC1.24
  Signal_2 w0.15: X5.5 7.155,15.72 7.735,16.3 v1(10.2,16.3)
PB13: IC1.25 X4.5 | length 7.1
  Top Layer w0.15: X4.5 5.325,16.745 8.635,16.745 9.263,16.117 9.263,15.415 9.328,15.35 IC1.25
PB14: IC1.26 X5.4 | length 5.5
  Top Layer w0.15: v1(8.385,15.763) 8.385,15.126 8.661,14.85 IC1.26
  Signal_2 w0.15: X5.4 8.385,14.725 v1(8.385,15.763)
PB15: IC1.27 X4.4 | length 6.4
  Top Layer w0.15: X4.4 5.736,14.616 8.11,14.616 8.232,14.616 8.485,14.363 9.938,14.363 IC1.27
PC6: IC1.30 X2.4 | length 20.6
  Top Layer w0.15: IC1.30 11.318,12.85 v1(11.75,13.282) ; X2.4@11.92,3.02 X2.4@11.97,3.07
  Signal_2 w0.15: v1(11.75,13.282) 11.073,13.959 11.073,15.547 11.432,15.906 12.648,15.906 12.873,15.681 12.884,15.681 13.958,14.607 13.958,11.322 11.92,9.284 X2.4@11.92,3.02
PC7: IC1.31 X2.3 | length 13.3
  Top Layer w0.15: IC1.31 12.618,12.35 v1(12.619,12.349)
  Signal_2 w0.15: X2.3@9.38,3.02 9.38,8.45 12.619,11.689 v1(12.619,12.349)
PC13: IC1.1 R3.2 | length 30.3
  Top Layer w0.15: v1(17.55,9.125) 17.556,9.131 17.556,9.785 17.621,9.85 IC1.1@18.02,9.85 ; R3.2@29.665,9.593 31.007,9.593 v1(31.1,9.5)
  Signal_2 w0.15: v1(17.55,9.125) 17.55,5.974 18.55,4.975 30.69,4.975 31.697,3.967 33.172,3.967 33.941,4.737 33.941,8.418 32.894,9.465 31.135,9.465 v1(31.1,9.5)
PD0: IC1.38 X5.1 | length 7.1
  Top Layer w0.15: X5.1 10.372,5.56 11.75,6.938 IC1.38
PD1: IC1.39 X4.1 | length 11.1
  Top Layer w0.15: X4.1 5.57,4.29 8.265,4.29 9.14,5.165 10.402,5.165 12.22,6.984 12.22,8.52 IC1.39
PD2: IC1.40 X2.2 | length 9.1
  Top Layer w0.15: X2.2@6.84,3.02 7.89,3.02 9.495,4.625 10.286,4.625 12.75,7.089 IC1.40
PD3: IC1.41 X2.1 | length 14.4
  Top Layer w0.15: X2.1 5.325,1.595 9.936,1.595 10.405,2.064 10.405,4.32 13.25,7.165 IC1.41
Reset: C1.1 IC1.10 X3.2 | length 20.7
  Top Layer w0.15: IC1.10@18.02,14.35 18.027,14.357 19.051,14.357 19.884,15.189 C1.1@19.884,15.614 ; C1.1 20,15.85 20.225,16.075 20.275,16.075 20.902,16.702 22.455,16.702 22.782,16.375 v1(22.87,16.375)
  Signal_2 w0.15: v1(22.87,16.375) 26.585,16.375 30.519,12.441 30.519,9.339 30.981,8.877 31.563,8.877 32.24,8.2 X3.2@32.24,8.1
pads on no net: NPN1.0 NPN2.0 NPN3.0

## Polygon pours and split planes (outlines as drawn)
3V3 on Signal_1 "3V3_L02_P002" (solid, pour order 2): 37,24 37,0 0,0 0,24
3V3A on Signal_1 "3V3A_L02_P001" (solid, pour order 1): 25.55,14.52 24.55,13.52 21.238,13.52 20.8,13.082 20.8,12.171 21.201,11.77 33.32,11.77 33.55,12 33.55,14.244 33.274,14.52
GND on Top Bottom "GND_L04_P000" (solid, pour order 0): 0,24 37,24 37,0 0,0

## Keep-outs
Keep-Out Layer:
  lines w0.05: 0,24 0,0 37,0 ; 0,24 37,24 ; 0,24 37,24 ; 0,24 0,0.5 0.5,0 37,0 ; 37,0 37,24 ; 37,0 37,1.289 37,2.381 37,4.444 37,6.75 37,23.5 37,24 ; 37,24 37,24

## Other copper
Top Layer:
  text ".Layer_Name" at 74.375,37.525 h1.2
  text ".Layer_Name" at 39.939,37.495 h1.2
Signal_1:
  text ".Layer_Name" at 74.375,37.525 h1.2
  text ".Layer_Name" at 39.935,37.489 h1.2
Signal_2:
  text ".Layer_Name" at 74.375,37.525 h1.2
  text ".Layer_Name" at 39.935,37.489 h1.2
Top Bottom:
  text ".Layer_Name" at 74.375,37.525 h1.2
  text ".Layer_Name" at 39.939,37.495 h1.2

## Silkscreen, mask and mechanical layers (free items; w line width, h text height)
Top Overlay:
  lines w0.2: 22.5,10.66 23.39,9.769 23.885,9.769
  text ".Layer_Name" at 74.375,35.525 h1.2
  text ".Layer_Name" at 39.875,35.5 h1.2
  text "Variant:" at 91.925,32.675 h1.2
  text "G" at 1.464,22.379 h0.8
  text "A4" at 13.794,22.345 h0.8
  text "A5" at 16.334,22.345 h0.8
  text "A6" at 18.874,22.345 h0.8
  text "A7" at 21.414,22.345 h0.8
  text "A3" at 23.954,22.345 h0.8
  text "A2" at 26.494,22.345 h0.8
  text "A1" at 29.167,22.345 h0.8
  text "A0" at 31.574,22.345 h0.8
  text "B3" at 3.6,22.3 h0.8
  text "B2" at 6.174,22.3 h0.8
  text "B1" at 8.847,22.3 h0.8
  text "B0" at 11.254,22.3 h0.8
  text "G-Board G070 Rev 0.3" at 7.316,19.141 h0.9
  text "B5" at 1.2,17.594 h0.8 r90
  text "B4" at 2.45,17.594 h0.8 r90
  text "A14" at 34.15,17.3 h0.8 r90
  text "A14" at 35.55,17.26 h0.8 r90
  text "B13" at 1.2,14.945 h0.8 r90
  text "B12" at 2.45,14.945 h0.8 r90
  text "A13" at 34.15,14.72 h0.8 r90
  text "3V3" at 35.55,14.654 h0.8 r90
  text "B15" at 1.2,12.18 h0.8 r90
  text "B14" at 2.45,12.18 h0.8 r90
  text "3V3A" at 34.15,11.334 h0.8 r90
  text "G" at 34.15,10.333 h0.8 r90
  text "A8" at 1.2,9.974 h0.8 r90
  text "B7" at 2.45,9.974 h0.8 r90
  text "R" at 34.15,7.885 h0.8 r90
  text "B6" at 1.2,7.434 h0.8 r90
  text "A15" at 2.45,7.1 h0.8 r90
  text "erb-pcb0004" at 8.565,5.303 h0.8
  text "G" at 34.15,5.233 h0.8 r90
  text "D0" at 2.372,4.894 h0.8 r90
  text "D1" at 1.25,4.867 h0.8 r90
  text "G" at 1.411,0.911 h0.8
  text "D3" at 3.65,0.895 h0.8
  text "D2" at 6.174,0.895 h0.8
  text "C7" at 8.714,0.895 h0.8
  text "C6" at 11.254,0.895 h0.8
  text "B8" at 13.834,0.895 h0.8
  text "B9" at 16.334,0.895 h0.8
  text "B10" at 18.54,0.895 h0.8
  text "B11" at 21.214,0.895 h0.8
  text "A12" at 23.47,0.904 h0.8
  text "A11" at 26.163,0.866 h0.8
  text "PA9" at 28.634,0.866 h0.8
  text "PA10" at 31.406,0.866 h0.8
Bottom Overlay:
  text ".Layer_Name" at 74.375,35.525 h1.2
  text ".Layer_Name" at 39.875,35.5 h1.2
  text "Variant:" at 91.925,32.675 h1.2
  text "G-Board-G070" at 20.85,16.95 h0.8
  text "erb-pcb0004" at 20.85,15.717 h0.8
  text "10/04/2025" at 20.85,14.45 h0.8
  text ".VersionControl_ProjFolderRevNumberShort" at 17.8,6.8 h1
  text "Git:" at 21.1,6.8 h1
Top Paste:
  text ".Layer_Name" at 74.375,33.525 h1.2
  text ".Layer_Name" at 39.875,33.5 h1.2
Bottom Paste:
  text ".Layer_Name" at 74.375,33.525 h1.2
  text ".Layer_Name" at 39.875,33.5 h1.2
Top Solder:
  text ".Layer_Name" at 74.375,31.525 h1.2
  text ".Layer_Name" at 39.875,31.5 h1.2
Bottom Solder:
  text ".Layer_Name" at 74.375,31.575 h1.2
  text ".Layer_Name" at 39.875,31.55 h1.2
Mechanical 1:
  lines w0.05: 37,0.5 37,23.5 ; 0,0.5 0,0.5 ; 0,0.5 0,23.5 ; 0,23.5 0,23.5 ; 0,0 0,24 37,24 37,0 0,0
  text ".Layer_Name" at 74.375,29.825 h1.2
  text ".Layer_Name" at 39.875,29.8 h1.2
Mechanical 2:
  text ".Layer_Name" at 74.375,28.025 h1.2
  text ".Layer_Name" at 39.875,28 h1.2
  text "all dimensions in mm" at 4.554,-2.246 h1.52
Drill Drawing:
  circle w0.254: c40.887,-1.238 r0.383
  lines w0.254: 40.503,-5.071 41.27,-5.071 41.27,-4.304 40.503,-4.304 40.503,-5.071 ; 40.503,-2.579 41.27,-2.579 40.887,-3.346 40.503,-2.579
  lines w0.381: 39.494,4.413 45.76,4.413 59.702,4.413 72.611,4.413 82.42,4.413 91.047,4.413 ; 39.494,6.185 45.76,6.185 59.702,6.185 72.611,6.185 82.42,6.185 91.047,6.185 ; 39.494,7.957 45.76,7.957 59.702,7.957 72.611,7.957 82.42,7.957 91.047,7.957 ; 39.494,9.729 45.76,9.729 59.702,9.729 72.611,9.729 82.42,9.729 91.047,9.729 ; 39.494,11.501 45.76,11.501 59.702,11.501 72.611,11.501 82.42,11.501 91.047,11.501 ; 39.494,13.273 45.76,13.273 59.702,13.273 72.611,13.273 82.42,13.273 91.047,13.273 ; 39.494,15.045 45.76,15.045 59.702,15.045 72.611,15.045 82.42,15.045 91.047,15.045 ; 39.494,16.817 45.76,16.817 59.702,16.817 72.611,16.817 82.42,16.817 91.047,16.817 ; 39.494,18.589 45.76,18.589 59.702,18.589 72.611,18.589 82.42,18.589 91.047,18.589 ; 39.494,20.361 45.76,20.361 59.702,20.361 72.611,20.361 82.42,20.361 91.047,20.361 ; 39.494,22.133 91.047,22.133 ; 39.772,-5.588 122.154,-5.588 ; 39.772,-0.414 122.154,-0.414 ; 45.76,23.905 45.76,2.641 ; 46.551,-7.313 46.551,1.311 ; 53.037,-7.313 53.037,1.311 ; 59.702,23.905 59.702,2.641 ; 66.074,-7.313 66.074,1.311 ; 72.335,-7.313 72.335,1.311 ; 72.611,23.905 72.611,2.641 ; 81.217,-7.313 81.217,1.311 ; 82.42,23.905 82.42,2.641 ; 97.473,-7.313 97.473,1.311 ; 104.7,-7.313 104.7,1.311 ; 113.72,-7.313 113.72,1.311 ; 45.76,2.641 39.494,2.641 39.494,23.905 91.047,23.905 91.047,2.641 82.42,2.641 ; 45.76,2.641 59.702,2.641 ; 59.702,2.641 72.611,2.641 ; 72.611,2.641 82.42,2.641 ; 39.772,-7.313 122.154,-7.313 122.154,1.311 39.772,1.311 39.772,-7.313
  text "PCB File:" at 91.925,36.675 h1.2
  text ".Pcb_File_Name_No_Path" at 105.425,36.675 h1.2
  text "Print Date:" at 91.925,34.675 h1.2
  text ".Print_Date" at 105.425,34.675 h1.2
  text "Variant:" at 91.925,32.675 h1.2
  text ".VariantName" at 105.425,32.675 h1.2
  text "Layer" at 40.634,22.576 h0.89
  text "Name" at 46.9,22.576 h0.89
  text "Material" at 60.842,22.576 h0.89
  text "Thickness" at 73.751,22.576 h0.89
  text "Constant" at 83.56,22.576 h0.89
  text "Top Overlay" at 46.9,20.804 h0.89
  text "Top Solder" at 46.9,19.032 h0.89
  text "Solder Resist" at 60.842,19.032 h0.89
  text "0,025mm" at 73.751,19.032 h0.89
  text "3.5" at 83.56,19.032 h0.89
  text "1" at 40.634,17.26 h0.89
  text "Top Layer" at 46.9,17.26 h0.89
  text "0,035mm" at 73.751,17.26 h0.89
  text "Dielectric 2" at 46.9,15.488 h0.89
  text "PP-006" at 60.842,15.488 h0.89
  text "0,200mm" at 73.751,15.488 h0.89
  text "4.1" at 83.56,15.488 h0.89
  text "2" at 40.634,13.716 h0.89
  text "Signal_1" at 46.9,13.716 h0.89
  text "CF-004" at 60.842,13.716 h0.89
  text "0,018mm" at 73.751,13.716 h0.89
  text "Dielectric 1" at 46.9,11.944 h0.89
  text "FR-4" at 60.842,11.944 h0.89
  text "1,065mm" at 73.751,11.944 h0.89
  text "4.6" at 83.56,11.944 h0.89
  text "3" at 40.634,10.172 h0.89
  text "Signal_2" at 46.9,10.172 h0.89
  text "CF-004" at 60.842,10.172 h0.89
  text "0,018mm" at 73.751,10.172 h0.89
  text "Dielectric 3" at 46.9,8.4 h0.89
  text "PP-006" at 60.842,8.4 h0.89
  text "0,200mm" at 73.751,8.4 h0.89
  text "4.1" at 83.56,8.4 h0.89
  text "4" at 40.634,6.628 h0.89
  text "Top Bottom" at 46.9,6.628 h0.89
  text "0,035mm" at 73.751,6.628 h0.89
  text "Bottom Solder" at 46.9,4.856 h0.89
  text "Solder Resist" at 60.842,4.856 h0.89
  text "0,025mm" at 73.751,4.856 h0.89
  text "3.5" at 83.56,4.856 h0.89
  text "Bottom Overlay" at 46.9,3.084 h0.89
  text "Symbol" at 40.807,0.103 h0.83
  text "Count" at 47.069,0.103 h0.83
  text "Hole Size" at 53.554,0.103 h0.83
  text "Plated" at 66.591,0.103 h0.83
  text "Hole Type" at 72.853,0.103 h0.83
  text "Drill Layer Pair" at 81.735,0.103 h0.83
  text "Via/Pad" at 97.99,0.103 h0.83
  text "Pad Shape" at 105.217,0.103 h0.83
  text "Template" at 114.237,0.103 h0.83
  text "2" at 47.069,-1.621 h0.69
  text "1,000mm (39,37mil)" at 53.554,-1.621 h0.69
  text "PTH" at 66.591,-1.621 h0.69
  text "Round" at 72.853,-1.621 h0.69
  text "Top Layer - Top Bottom" at 81.735,-1.621 h0.69
  text "Pad" at 97.99,-1.621 h0.69
  text "(Mixed)" at 105.217,-1.621 h0.69
  text "(Mixed)" at 114.237,-1.621 h0.69
  text "38" at 47.069,-3.346 h0.69
  text "0,300mm (11,81mil)" at 53.554,-3.346 h0.69
  text "PTH" at 66.591,-3.346 h0.69
  text "Round" at 72.853,-3.346 h0.69
  text "Top Layer - Top Bottom" at 81.735,-3.346 h0.69
  text "Via" at 97.99,-3.346 h0.69
  text "Rounded" at 105.217,-3.346 h0.69
  text "v60h30" at 114.237,-3.346 h0.69
  text "44" at 47.069,-5.071 h0.69
  text "1,100mm (43,31mil)" at 53.554,-5.071 h0.69
  text "PTH" at 66.591,-5.071 h0.69
  text "Round" at 72.853,-5.071 h0.69
  text "Top Layer - Top Bottom" at 81.735,-5.071 h0.69
  text "Pad" at 97.99,-5.071 h0.69
  text "(Mixed)" at 105.217,-5.071 h0.69
  text "(Mixed)" at 114.237,-5.071 h0.69
  text "84 Total" at 47.069,-6.795 h0.69

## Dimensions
0,0 to 0,24 on Mechanical 2
0,23.8 to 37,24 on Mechanical 2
